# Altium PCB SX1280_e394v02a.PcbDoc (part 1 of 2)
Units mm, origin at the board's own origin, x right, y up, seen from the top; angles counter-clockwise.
Board outline 104.5 x 58 mm, 4 copper layers (Top Layer, MidLayer1, MidLayer2, Bottom Layer), stack 0.995 mm thick; 155 components, 106 nets, 471 pads, 1470 vias.
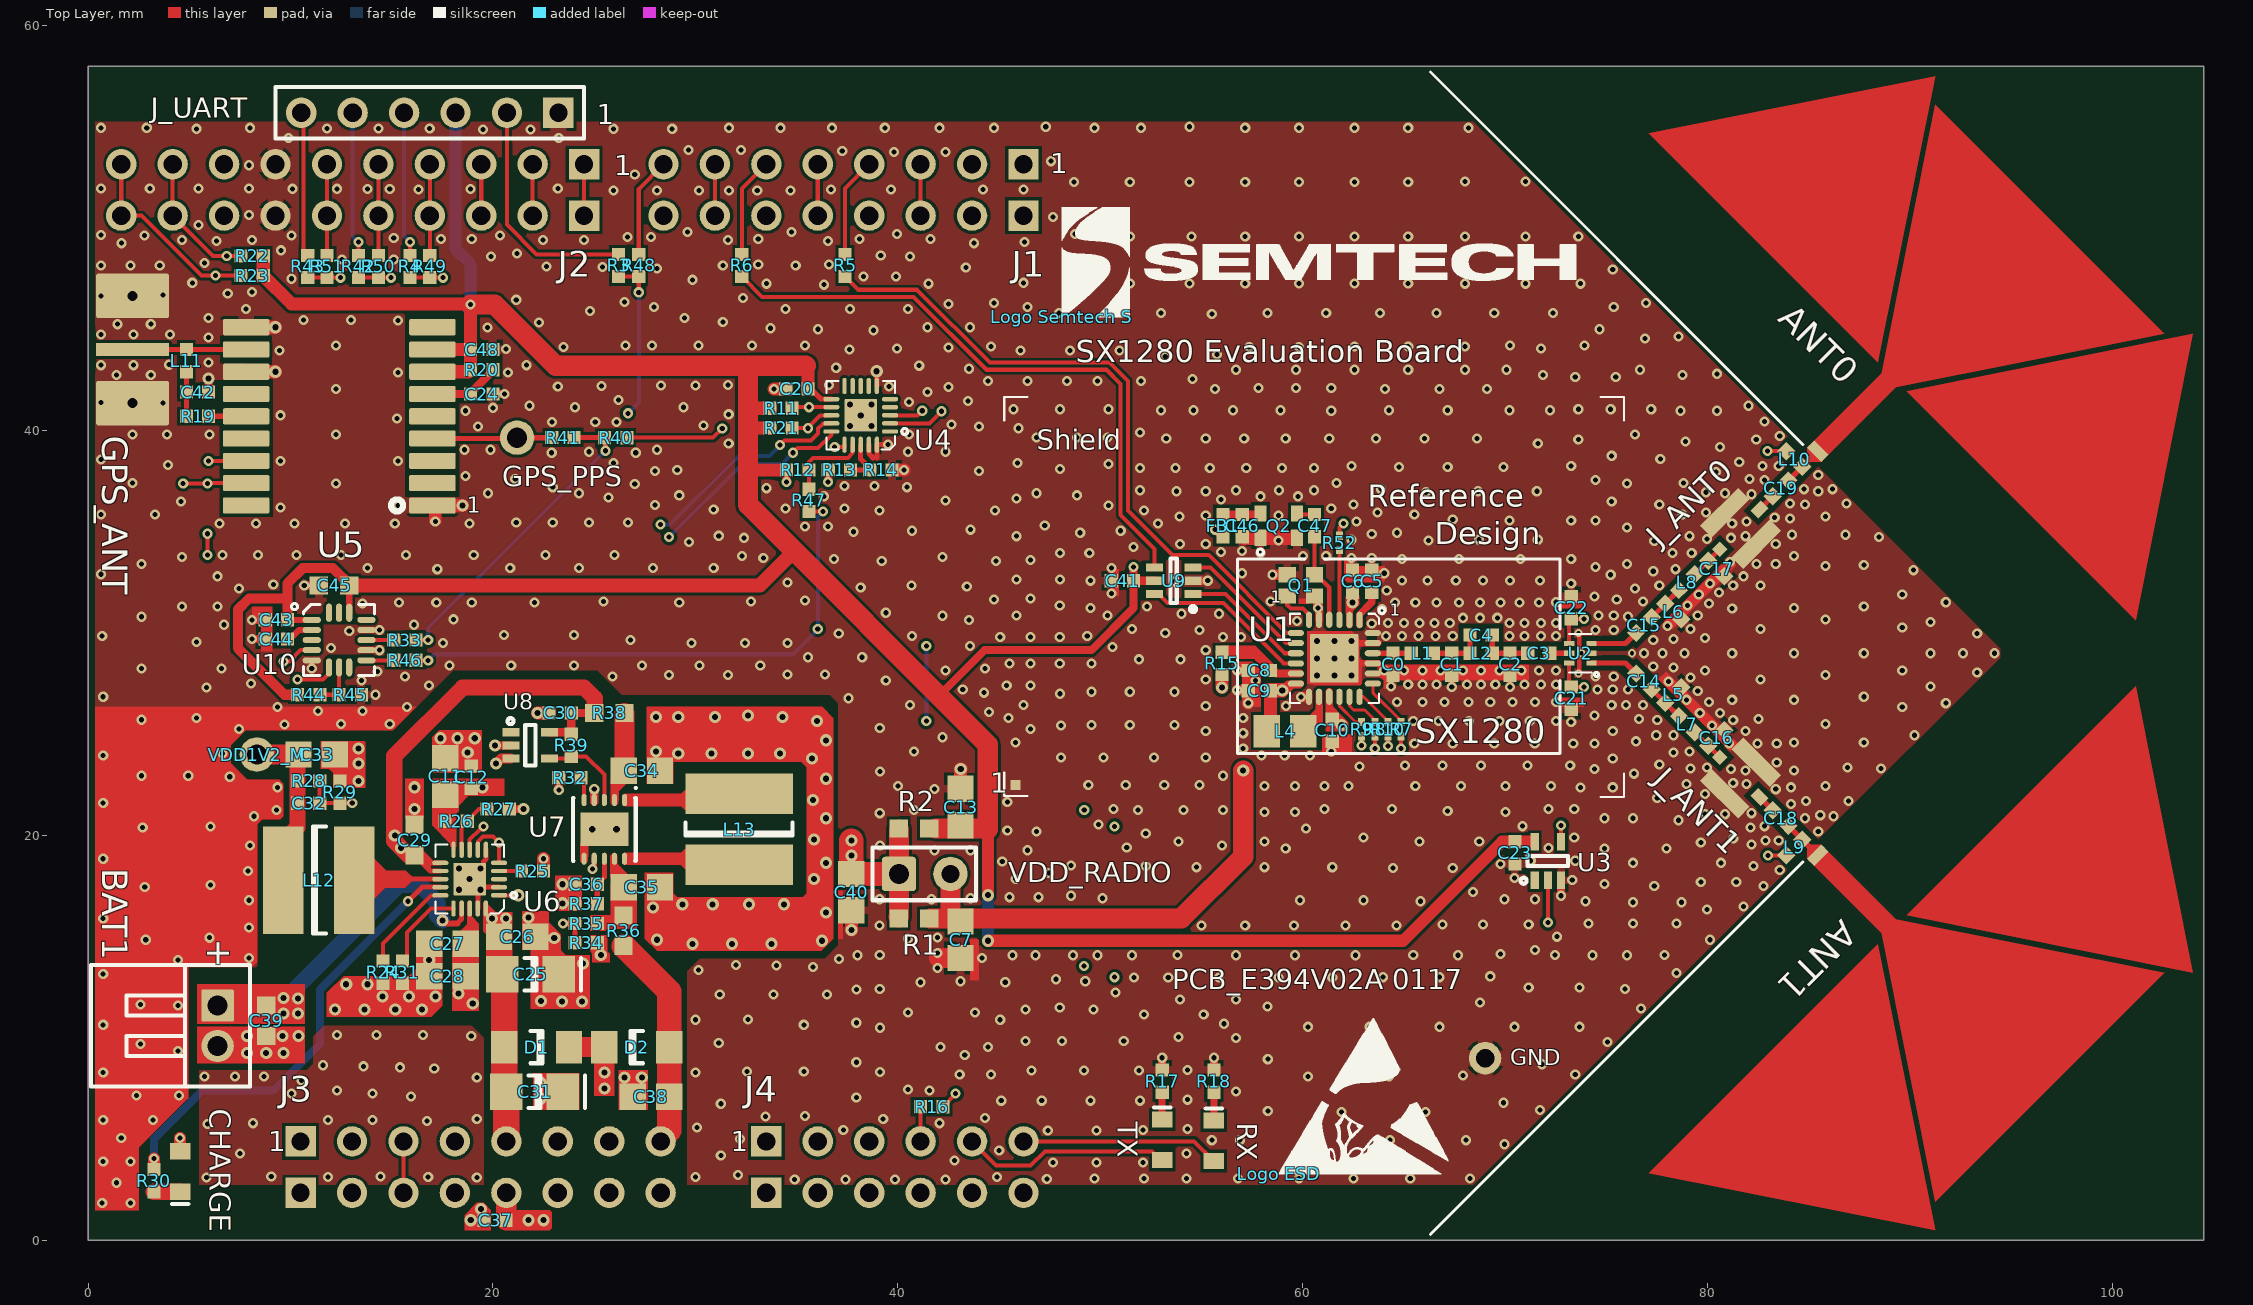
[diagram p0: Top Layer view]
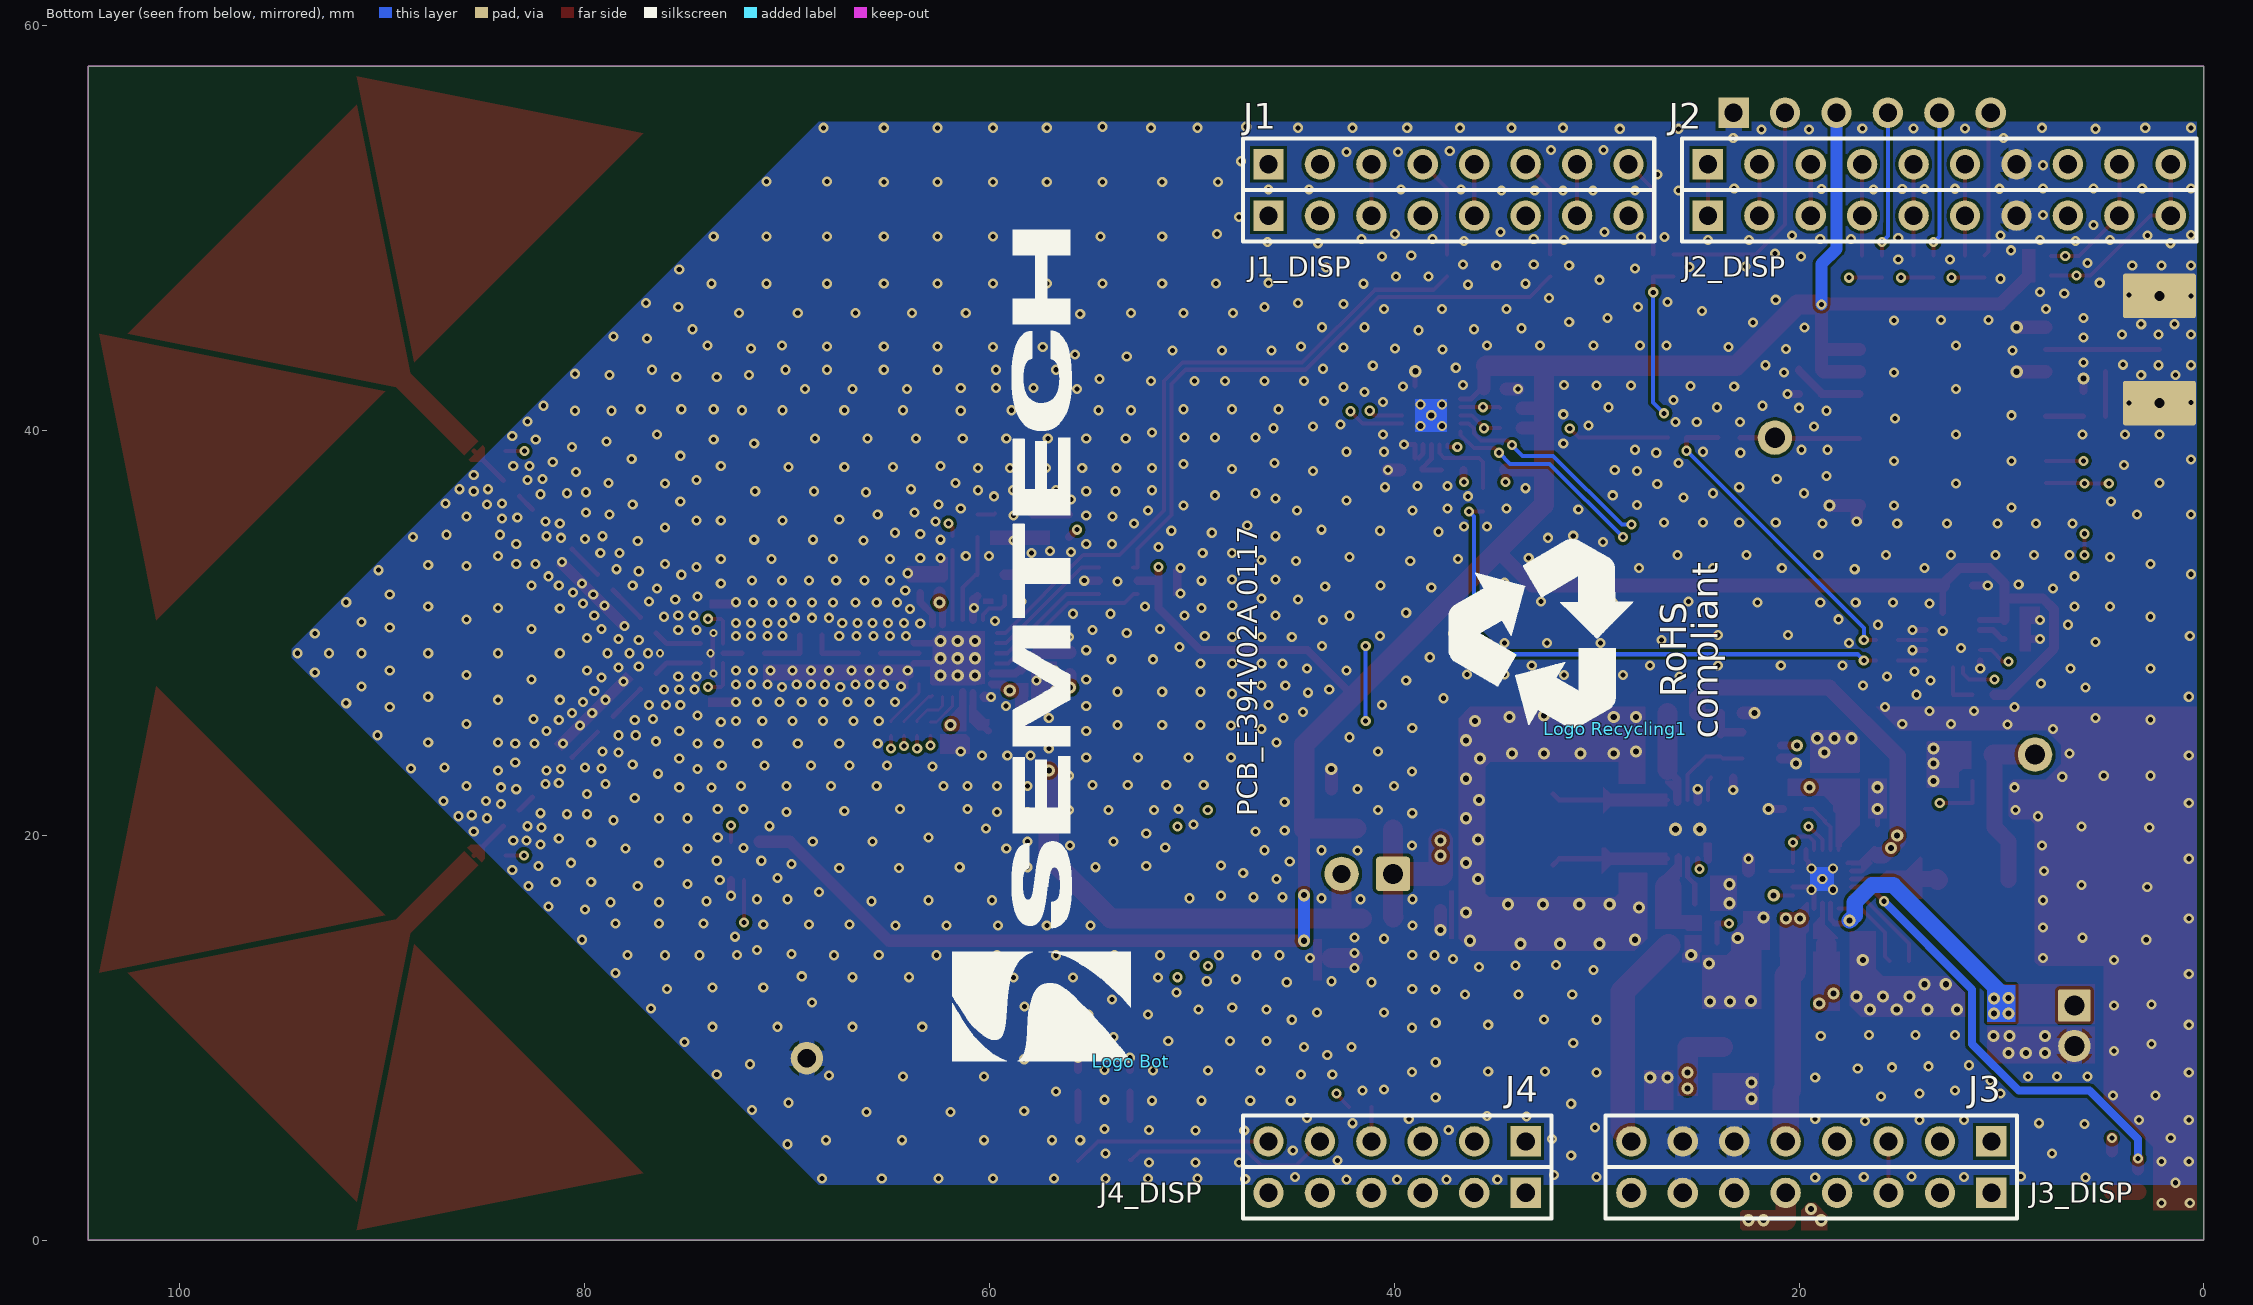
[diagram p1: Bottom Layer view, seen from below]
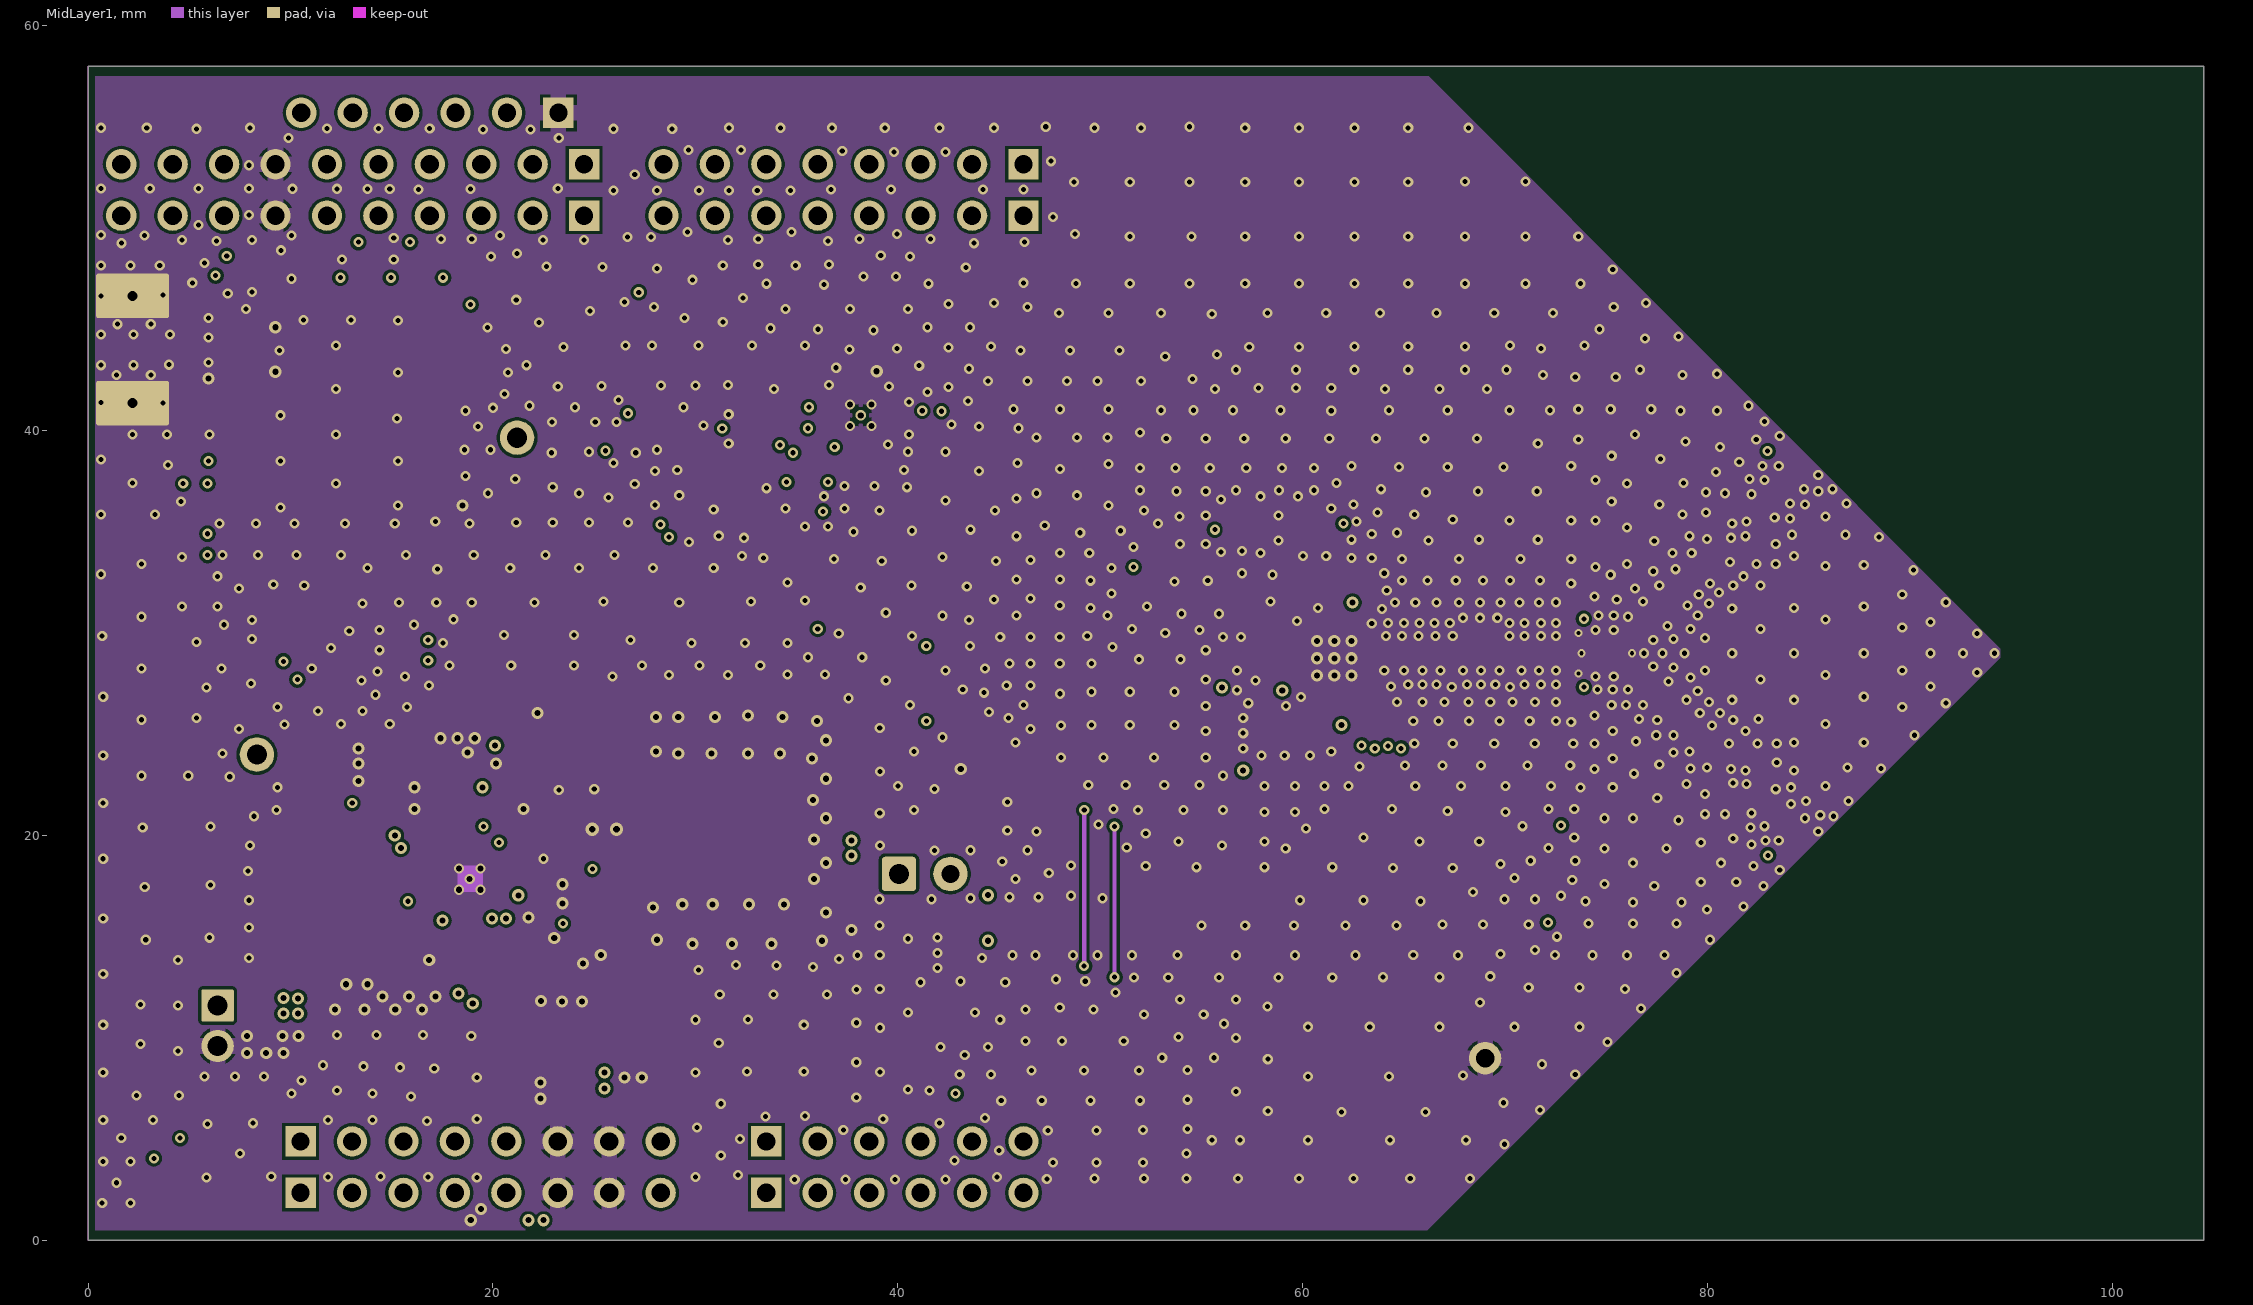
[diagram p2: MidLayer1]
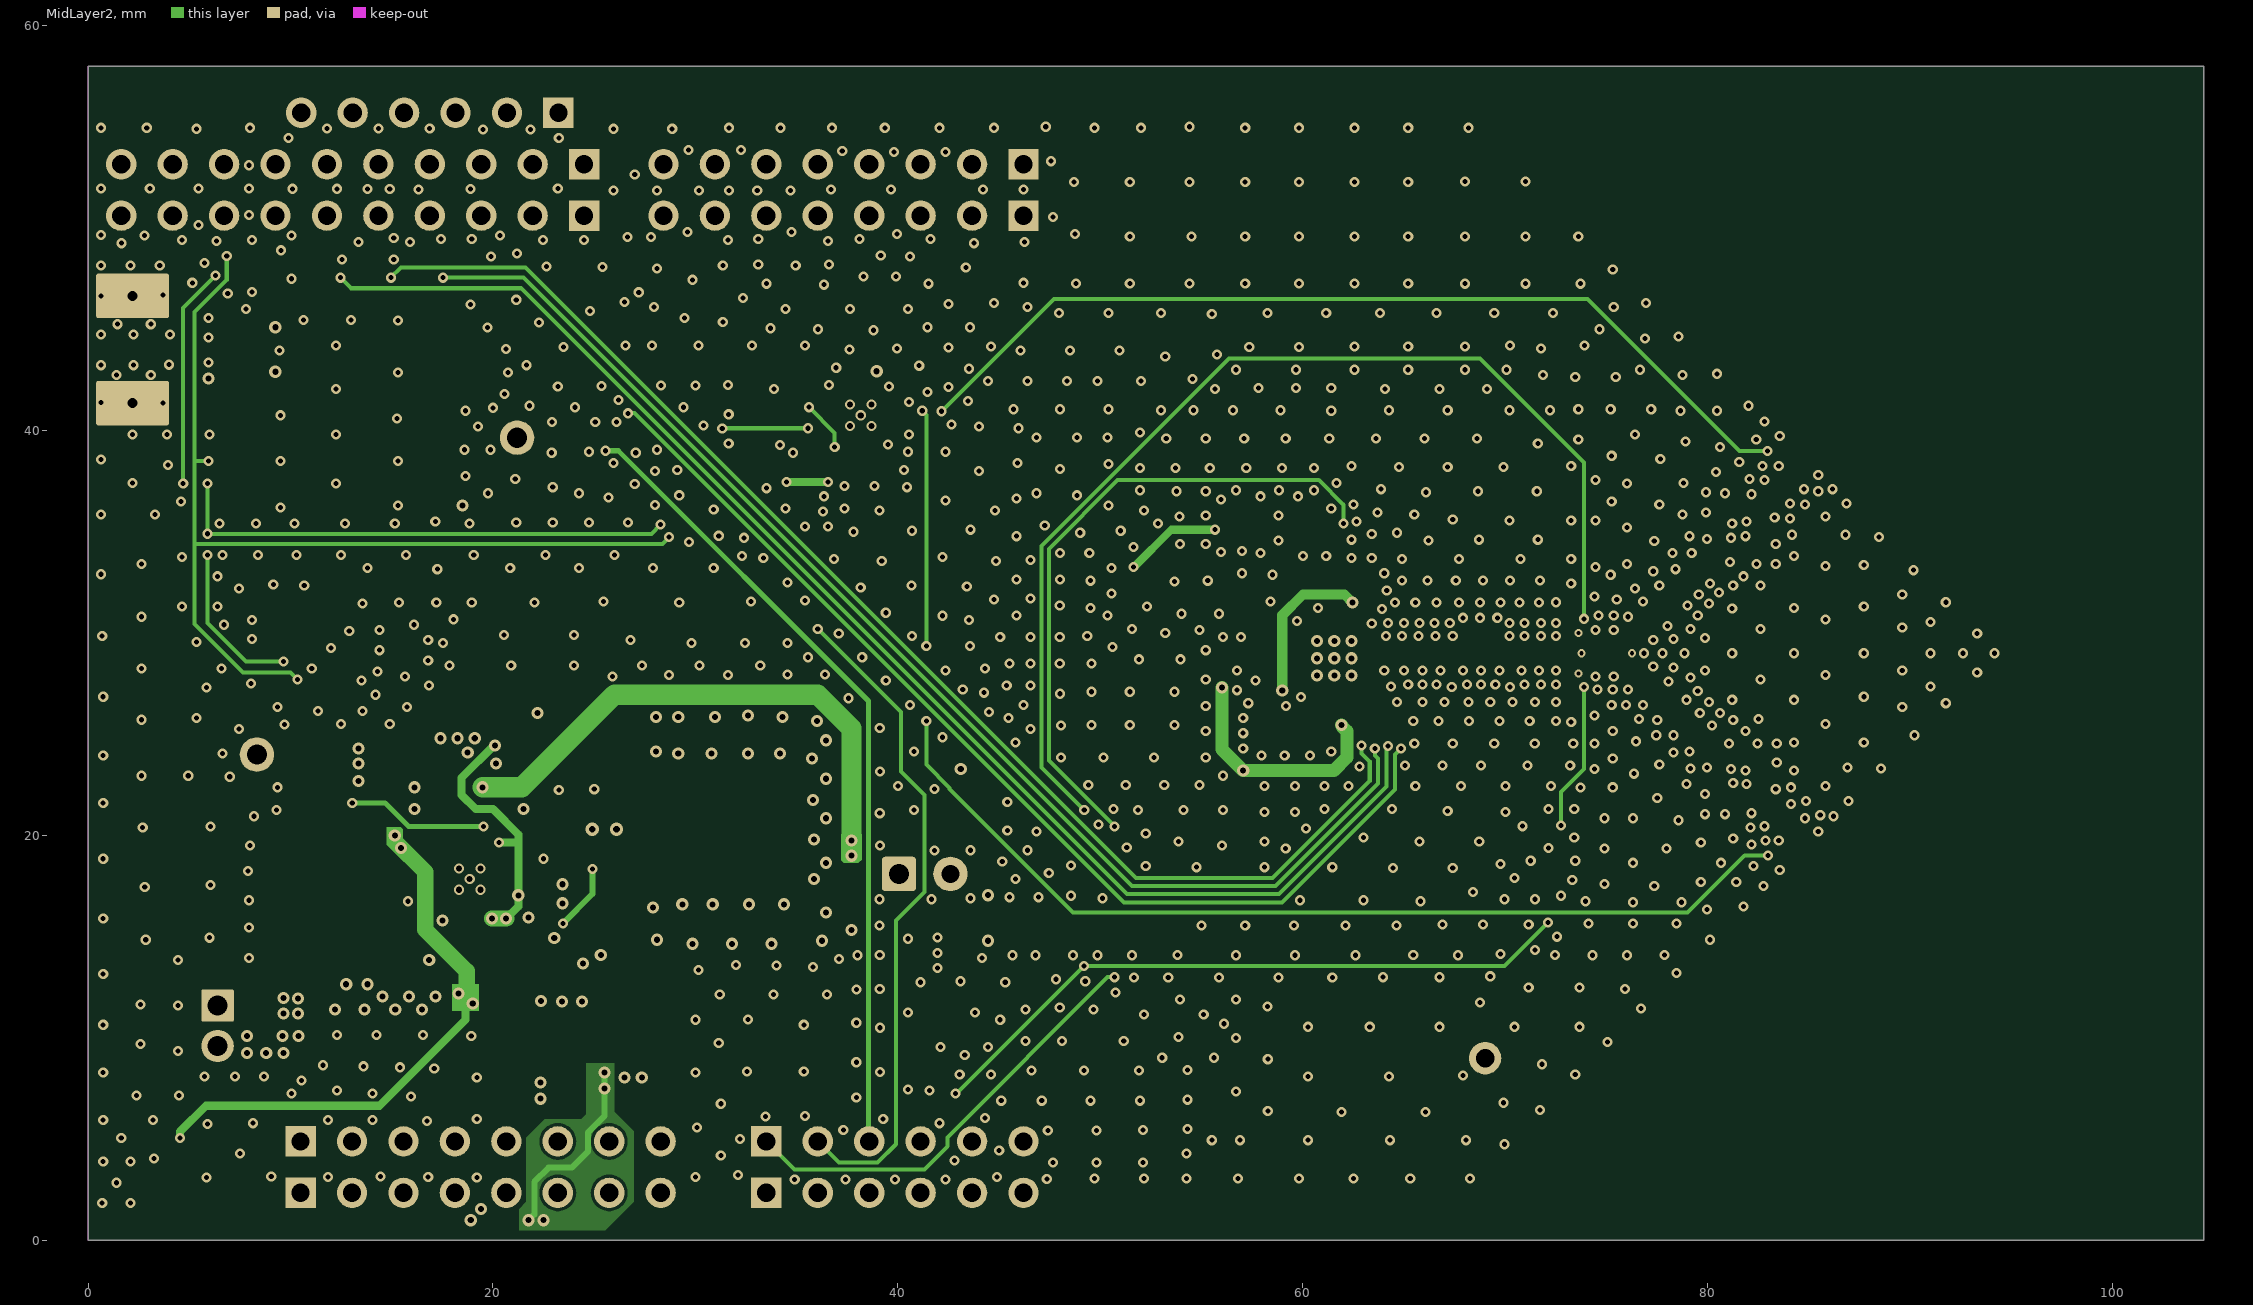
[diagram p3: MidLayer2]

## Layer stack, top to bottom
Top Layer: signal copper 0.035
Dielectric: core 0.127, FR-4, Dk 4.3
MidLayer1: signal copper 0.0356
Dielectric: prepreg 0.6, FR-4, Dk 4.8
MidLayer2: signal copper 0.0356
Dielectric: core 0.127, FR-4, Dk 4.8
Bottom Layer: signal copper 0.035

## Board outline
0,0 0,58 104.5,58 104.5,0

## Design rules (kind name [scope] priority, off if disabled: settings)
Clearance Clearance_RF_GND [InNet('GND') And OnLayer('Top Layer') And (InPolygon) vs InNet('NetC0_1') or InNet('NetC1_2')  or  InNet('NetC2_2') or InNet('NetC3_2')  or  InNet('NetC15_2')  or  InNet('NetC15_1')  or  InNet('NetC17_1') or  InNet('NetC19_2')  or  InNet('NetANT0_1')  or  InNet('NetC14_2')  or  InNet('NetC14_1')  or  InNet('NetC16_1') or  InNet('NetC18_2')  or  InNet('NetANT1_1')] p1: gap=0.25
Clearance Clearance_GND_Keepout [InNet('GND') vs OnLayer('Keep-Out Layer')] p2: gap=0.25
Clearance Clearance_GND [InNet('GND')] p3: gap=0.15
Clearance [All] p4: gap=0.15
ComponentClearance ComponentClearance_SMA_RFIO [InComponent('RFIO')] p1: gap=0 collisioncheckmode=3 verticalgap=0 showdistances=FALSE
ComponentClearance [All] p2: gap=0.2 collisioncheckmode=3 verticalgap=0.3 showdistances=FALSE
HoleSize [All] p1: absolutevalues=TRUE maxlimit=3.6 minlimit=0.2 maxpercent=80.000 minpercent=20.000
HoleToHoleClearance [All] p1: gap=0.2 allowstackedmicrovias=TRUE
MinimumSolderMaskSliver [All] p1: minsoldermaskwidth=0.04
PlaneClearance [All] p1: clearance=0.2
PlaneConnect [All] p1: planeconnectstyle=Direct reliefexpansion=0.508 reliefentries=4 reliefconductorwidth=0.254 reliefairgap=0.254
PolygonConnect "PolygonConnect SMD" [InNet('GND') vs HasFootprint('ND2016DA') or HasFootprint('rlc_603_smd') or HasFootprint('rlc_402_smd') or HasFootprint('rlc_402_smd diode') or hasFootprint('rlc_805_smd')  or hasFootprint('SC70-5')  or hasFootprint('TCXO 2.0x1.6mm')] p1: connectstyle=Relief reliefconductorwidth=0.4 reliefentries=4 polygonreliefangle="90 Angle"
PolygonConnect PolygonConnect_comp_diverse [InNet('GND') or  InNet('VDD') or  InNet('VDD_DISPLAY')  or  InNet('VDD_RADIO') vs HasFootprint('LGM676 LED') or  HasFootprint('BRIDGE_254MM') or  HasFootprint('pin_0.9mm') or HasFootprint('SMA_STRAIGHT')  or  HasFootprint('HDR2X8')   or  HasFootprint('HDR2X6')  or  HasFootprint('HDR1X10') or  HasFootprint('vqfn20_3x3mm') or  HasFootprint('HDR1X9') or  HasFootprint('HDR1X8')  or  HasFootprint('HDR1X6') or  HasFootprint('HDR1X4')   or  HasFootprint('MAX-7') or  HasFootprint('S2B-PH-K-S') or  HasFootprint('DD10_L')] p2: connectstyle=Relief reliefconductorwidth=0.8 reliefentries=4 polygonreliefangle="90 Angle"
PolygonConnect PolygonConnect_all [All] p3: connectstyle=Direct reliefconductorwidth=0.6 reliefentries=4 polygonreliefangle="90 Angle"
RoomDefinition SX1280_Power_Display_e394v02a [InComponentClass('SX1280_Power_Display_e394v02a')] p1: confinementstyle=ConfineOut formatcopy=TRUE lockcomponents=FALSE outline 81.8,81 81.8,123.8 82,124 122,124 122,81
RoomDefinition SX1280_e394v02a [InComponentClass('SX1280_e394v02a')] p2: confinementstyle=ConfineOut formatcopy=TRUE lockcomponents=FALSE outline 13.5,81.35 13.45,81.4 13.45,124.35 67.45,124.35 67.3,124.2 67.3,81.35
RoutingVias [All] p1: holewidth=0.3 width=0.6 viastyle="Through Hole" minholewidth=0.2 minwidth=0.4 maxholewidth=0.4 maxwidth=0.8
SilkToSilkClearance [All] p1: silktosilkclearance=0.05
SilkscreenOverComponentPads [All] p1: minsilkscreentomaskgap=0.05
SolderMaskExpansion [All] p1: expansion=0.05
Width "Width GND" [InNet('GND')] p1: maxlimit=3 minlimit=0.2 preferedwidth=0.4
Width Width_VCC [InNet('VDD') or  InNet('VDD_DISPLAY') or  InNet('VDD_RADIO')] p2: maxlimit=2 minlimit=0.2 preferedwidth=0.8
Width "Width All" [All] p3: maxlimit=2 minlimit=0.15 preferedwidth=0.2
20 further rules are at their usual default settings.

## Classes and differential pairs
component class SX1280_Power_Display_e394v02a: BAT1 C11 C12 C24 C25 C26 C27 C28 C29 C30 C32 C33 C34 C35 C36 C37 C39 C42 C43 C44 C45 C46 C47 C48 CHARGE D1 D2 FB1 GPS_ANT GPS_PPS J1_DISP J2_DISP J3_DISP J4_DISP L11 L12 L13 Q2 R19 R20 R24 R25 R26 R27 R28 R29 R30 R31 R32 R33 R34 R35 R36 R37 R38 R39 R41 R44 R45 R46 U5 U6 U7 U8 U10 VDD1V2_M
component class SX1280_e394v02a: ANT0 ANT1 C0 C1 C2 C3 C4 C5 C6 C7 C8 C9 C10 C13 C14 C15 C16 C17 C18 C19 C20 C21 C22 C23 C31 C38 C40 C41 GND J1 J2 J3 J4 J_ANT0 J_ANT1 J_UART L1 L2 L4 L5 L6 L7 L8 L9 L10 "Logo Bot" "Logo ESD" "Logo Recycling1" "Logo Semtech S" Q1 R1 R2 R3 R4 R5 R6 R7 R8 R9 R10 R11 R12 R13 R14 R15 R16 R17 R18 R21 R22 R23 R40 R42 R43 R47 R48 R49 R50 R51 R52 RFIO RX Shield TX U1 U2 U3 U4 U9 VDD_RADIO

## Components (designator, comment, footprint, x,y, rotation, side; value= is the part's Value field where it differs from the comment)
ANT0 "Antenna" ANT_2.4GHz_microstrip 85.43,38.98 r315 top locked
ANT1 "Antenna" ANT_2.4GHz_microstrip 85.43,19.02 r225 top locked
BAT1 "Battery" S2B-PH-K-S 6.4,11.6 r270 top
C0 "Cap" RLC_402_SMD 64.45,28.45 r270 top
C1 "Cap" RLC_402_SMD 67.35,28.45 r90 top
C2 "Cap" RLC_402_SMD 70.228,28.45 r90 top
C3 "Cap" RLC_402_SMD 71.65,29 r0 top
C4 "Cap" RLC_402_SMD 68.8,29.9 r0 top
C5 "Cap" rlc_402_smd 63.4,32.55 r270 top
C6 "Cap" RLC_402_SMD 62.45,32.55 r270 top
C7 "Cap" rlc_805_smd 43.09,14.85 r90 top
C8 "Cap" RLC_402_SMD 57.85,28.15 r0 top
C9 "Cap" RLC_402_SMD 57.85,27.15 r0 top
C10 "Cap" RLC_402_SMD 61.45,25.2 r90 top
C11 "Cap" rlc_805_smd 17.649,22.917 r270 top
C12 "Cap" RLC_402_SMD 18.925,22.884 r270 top
C13 "Cap" rlc_805_smd 43.09,21.4 r270 top
C14 "Cap" RLC_402_SMD 76.839,27.611 r135 top
C15 "Cap" RLC_402_SMD 76.839,30.389 r225 top
C16 "Cap" RLC_402_SMD 80.41,24.818 r45 top
C17 "Cap" RLC_402_SMD 80.41,33.182 r315 top
C18 "Cap" RLC_402_SMD 83.592,20.858 r135 top
C19 "Cap" RLC_402_SMD 83.592,37.142 r225 top
C20 "Cap" RLC_402_SMD 35.011,42.05 r180 top
C21 "Cap" RLC_402_SMD 73.25,26.775 r90 top
C22 "Cap" RLC_402_SMD 73.25,31.25 r270 top
C23 "Cap" RLC_402_SMD 70.47,19.139 r90 top
C24 "Cap" RLC_402_SMD 19.445,41.8 r0 top
C25 "Cap Pol" CD3216-1206 21.85,13.144 r0 top
C26 "Cap" rlc_805_smd 21.2,14.994 r180 top
C27 "Cap" rlc_805_smd 17.75,14.644 r0 top
C28 "Cap" rlc_805_smd 17.75,13.044 r0 top
C29 "Cap" rlc_603_smd 16.125,19.775 r270 top
C30 "Cap" RLC_402_SMD 23.317,26.05 r0 top
C31 "Cap Pol" CD3216-1206 22.05,7.35 r0 top
C32 "Cap" RLC_402_SMD 10.892,21.594 r180 top
C33 "Cap" rlc_805_smd 11.292,23.994 r180 top
C34 "Cap" rlc_805_smd 27.35,23.2 r180 top
C35 "Cap" rlc_805_smd 27.35,17.45 r180 top
C36 "Cap" RLC_402_SMD 24.6,17.589 r0 top
C37 "Cap" RLC_402_SMD 20.1,1 r0 top
C38 "Cap" rlc_805_smd 27.8,7.1 r0 top
C39 "Cap" rlc_603_smd 8.8,10.85 r90 top
C40 "Cap" rlc_805_smd 37.7,17.2 r90 top
C41 "Cap" RLC_402_SMD 51.084,32.58 r0 top
C42 "Cap" RLC_402_SMD 5.407,41.9 r0 top
C43 "Cap" RLC_402_SMD 9.3,30.65 r0 top
C44 "Cap" RLC_402_SMD 9.3,29.7 r0 top
C45 "Cap" rlc_603_smd 12.15,32.35 r0 top
C46 "Cap" RLC_402_SMD 57,35.3 r90 top
C47 "Cap" RLC_402_SMD 60.575,35.3 r270 top
C48 "Cap" RLC_402_SMD 19.445,44 r0 top
CHARGE "LED" "LGM676 LED" 4.55,3.4 r270 top
D1 "D Schottky single" SOD123 22.15,9.55 r0 top
D2 "D Schottky single" SOD123 27.1,9.55 r180 top
FB1 "Ferrite beads" RLC_402_SMD 56.05,35.3 r90 top
GND "Test Pin" pin_0.9mm 69,9 r90 top
GPS_ANT "SMA End Launch" "SMA END LAUNCH JACK RECEPTACLE SHORT" 1.8,44 r270 top
GPS_PPS "Test Pin" pin_1mm 21.19,39.645 r90 top
J1 "Header 8" HDR1X8 46.2,53.15 r180 bottom locked
J1_DISP "Header 8" HDR1X8 46.2,50.61 r180 bottom locked
J2 "Header 10" HDR1X10 24.5,53.15 r180 bottom locked
J2_DISP "Header 10" HDR1X10 24.5,50.61 r180 bottom locked
J3 "Header 8" HDR1X8 10.5,4.89 r0 bottom locked
J3_DISP "Header 8" HDR1X8 10.5,2.35 r0 bottom locked
J4 "Header 6" HDR1X6 33.5,4.89 r0 bottom locked
J4_DISP "Header 6" HDR1X6 33.5,2.35 r0 bottom locked
J_ANT0 "MS-156HF" "MS-156HF Hirose" 81.665,35.215 r225 top
J_ANT1 "MS-156HF" "MS-156HF Hirose" 81.665,22.785 r135 top
J_UART "Header 6" HDR1X6 23.23,55.69 r180 top locked
L1 "Inductor" RLC_402_SMD 65.9,29 r0 top
L2 "Inductor" RLC_402_SMD 68.8,29 r0 top
L4 "Inductor" "rlc_805_smd enlarged" 59.12,25.15 r0 top
L5 "Inductor" RLC_402_SMD 78.288,26.939 r225 top
L6 "Inductor" RLC_402_SMD 78.288,31.061 r135 top
L7 "Inductor" RLC_402_SMD 78.96,25.49 r315 top
L8 "Inductor" RLC_402_SMD 78.96,32.51 r45 top
L9 "Inductor" RLC_402_SMD 84.263,19.408 r45 top
L10 "Inductor" RLC_402_SMD 84.263,38.59 r315 top
L11 "Inductor" RLC_402_SMD 4.857,43.45 r270 top
L12 "Inductor" L4818 11.4,17.8 r270 top
L13 "Inductor" L4818 32.15,20.3 r0 top
"Logo Bot" "Logo symbol" logo_semtech_horiz_size4 53,8.85 r90 bottom
"Logo ESD" "Logo symbol" "Logo ESD" 58.8,3.3 r0 top
"Logo Recycling1" "Logo symbol" "Logo Recycling1" 29.077,25.27 r90 bottom
"Logo Semtech S" "Logo symbol" logo_semtech_horiz_size3 48.1,45.61 r0 top
Q1 "Xtal" ND2016DA 59.9,32.35 r0 top
Q2 "TCXO" "TCXO 2.0x1.6mm" 58.8,35.3 r0 top
R1 "Resistor" rlc_603_smd 40.79,15.9 r180 top
R2 "Resistor" rlc_603_smd 40.79,20.35 r180 top
R3 "Resistor" RLC_402_SMD 26.2,48.15 r270 top
R4 "Resistor" RLC_402_SMD 15.9,48.1 r270 top
R5 "Resistor" RLC_402_SMD 37.39,48.15 r270 top
R6 "Resistor" RLC_402_SMD 32.286,48.15 r270 top
R7 "Resistor" rlc_201_smd 64.85,25.25 r90 top
R8 "Resistor" rlc_201_smd 63.55,25.25 r90 top
R9 "Resistor" rlc_201_smd 62.9,25.25 r90 top
R10 "Resistor" rlc_201_smd 64.2,25.25 r90 top
R11 "Resistor" RLC_402_SMD 34.225,41.1 r0 top
R12 "Resistor" RLC_402_SMD 35.05,38.05 r180 top
R13 "Resistor" RLC_402_SMD 37.111,38.05 r180 top
R14 "Resistor" RLC_402_SMD 39.161,38.05 r180 top
R15 "Resistor" RLC_402_SMD 56,28.5 r270 top
R16 "Resistor" RLC_402_SMD 41.667,6.6 r180 top
R17 "Resistor" RLC_402_SMD 53.05,7.871 r270 top
R18 "Resistor" RLC_402_SMD 55.6,7.871 r270 top
R19 "Resistor" RLC_402_SMD 5.407,40.7 r180 top
R20 "Resistor" RLC_402_SMD 19.445,43 r0 top
R21 "Resistor" RLC_402_SMD 34.225,40.125 r180 top
R22 "Resistor" RLC_402_SMD 8.1,48.625 r0 top
R23 "Resistor" RLC_402_SMD 8.1,47.65 r0 top
R24 "Resistor" RLC_402_SMD 14.575,13.25 r270 top
R25 "Resistor" RLC_402_SMD 21.95,18.244 r0 top
R26 "Resistor" RLC_402_SMD 18.18,20.7 r0 top
R27 "Resistor" RLC_402_SMD 20.25,21.3 r0 top
R28 "Resistor" RLC_402_SMD 10.892,22.694 r0 top
R29 "Resistor" RLC_402_SMD 12.442,22.144 r90 top
R30 "Resistor" RLC_402_SMD 3.25,2.95 r270 top
R31 "Resistor" RLC_402_SMD 15.531,13.25 r270 top
R32 "Resistor" RLC_402_SMD 23.8,22.85 r180 top
R33 "Resistor" RLC_402_SMD 15.65,29.65 r0 top
R34 "Resistor" RLC_402_SMD 24.6,14.7 r180 top
R35 "Resistor" RLC_402_SMD 24.6,15.65 r0 top
R36 "Resistor" rlc_603_smd 26.45,15.294 r270 top
R37 "Resistor" RLC_402_SMD 24.6,16.625 r0 top
R38 "Resistor" rlc_603_smd 25.75,26.05 r0 top
R39 "Resistor" RLC_402_SMD 23.867,24.45 r270 top
R40 "Resistor" RLC_402_SMD 26.062,39.645 r0 top
R41 "Resistor" RLC_402_SMD 23.45,39.65 r0 top
R42 "Resistor" RLC_402_SMD 13.35,48.1 r270 top
R43 "Resistor" RLC_402_SMD 10.85,48.1 r270 top
R44 "Resistor" RLC_402_SMD 10.9,26.95 r0 top
R45 "Resistor" RLC_402_SMD 12.95,26.95 r0 top
R46 "Resistor" RLC_402_SMD 15.65,28.65 r0 top
R47 "Resistor" RLC_402_SMD 35.6,36.55 r90 top
R48 "Resistor" RLC_402_SMD 27.2,48.15 r270 top
R49 "Resistor" RLC_402_SMD 16.88,48.1 r270 top
R50 "Resistor" RLC_402_SMD 14.34,48.1 r270 top
R51 "Resistor" RLC_402_SMD 11.8,48.1 r270 top
R52 "Resistor" rlc_201_smd 61.8,34.45 r90 top
RX "LED" "LGM676 LED" 55.6,4.921 r90 top
Shield "Logo symbol" "BMIS-209-F - SHIELD" 45.8,22.5 r0 top locked
TX "LED" "LGM676 LED" 53.05,4.971 r90 top
U1 "SX1280" VQFN24_4X4MM 61.55,28.75 r270 top locked
U2 "RF Switch" MiniMold-6 73.7,29 r90 top
U3 "NC7SZ04" SC70-5 72.1,18.739 r90 top
U4 "SX9306" vqfn20_3x3mm 38.161,40.75 r180 top
U5 "MAX-7Q GPS" MAX-7 12.41,40.7 r0 top
U6 "LTC3553" vqfn20_3x3mm 18.85,17.844 r180 top
U7 "LTC3127" DD10_L 25.5,20.3 r270 top
U8 "NC7SZ04" SC70-5 21.842,24.446 r0 top
U9 "74LVC1G332GW" SOT363-6 53.619,32.58 r180 top
U10 "MMA8451Q" VQFN16_3X3MM 12.4,29.65 r0 top
VDD1V2_M "Test Pin" pin_1mm 8.342,23.994 r270 top
VDD_RADIO "Jumper" BRIDGE_254MM 40.05,18.1 r0 top

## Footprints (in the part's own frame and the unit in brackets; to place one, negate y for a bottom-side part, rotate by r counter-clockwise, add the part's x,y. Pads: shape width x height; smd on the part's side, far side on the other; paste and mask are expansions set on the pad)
ANT_2.4GHz_microstrip [mm] "Antenna 2.4 GHz ISM band - Microstrip"
  rect 1x0.5 smd paste-1 mask-1: 1(0,0)
  Top Layer region: 8,16.2 -8,16.2 -0.5,4.95 -0.5,0.2 0.5,0.2 0.5,4.95
  Top Layer region: 1,5.2 17,5.2 9,17.2
  Top Layer region: -17,5.2 -1,5.2 -9,17.2
  body extent -0.5,-0.25 0.5,0.2, height 2.95
"BMIS-209-F - SHIELD" [mm] "BMIS-209-F EMI Gasket - modif SolderMask - Standard Surface Mount Shields -  Laird Technologies"
  rect 0.5x0.5 smd paste-1 mask+0.05: 1(0,0)
  Mechanical 15 keep-out lines w1: 0,0 29.5,0 29.5,18.6 0,18.6 0,0
  silkscreen extent -0.55,-0.6 30.05,19.15, body extent -0.3,-0.3 0.3,0.3, height 0.8
BRIDGE_254MM [mm] "Generic Bridge 2.54mm, 2 Leads 0.9mm;"
  rrect20% 1.7x1.7 hole 1 paste+0 mask+0.05: 1(0,0)
  round 1.7 hole 0.9 paste+0 mask+0.05: 2(2.54,0)
  silkscreen extent -1.3,-1.3 3.8,1.3, body extent -1.4,-1.4 3.9,1.4, height 1
CD3216-1206 [mm] "Chip Diode; Body 3.2 x 1.6 mm (LxW typ)"
  rect 1.6x1.8 smd mask+0.05: 1(-1.4,0) 2(1.4,0)
  silkscreen extent -0.3,-0.8 2.5,0.8
DD10_L [mm] "SON, 10-Leads, Body 3x3 mm, Pitch 0.5mm, IPC High Density"
  oval 0.6x0.25 smd: 1(-1.45,1) 2(-1.45,0.5) 3(-1.45,0) 4(-1.45,-0.5) 5(-1.45,-1) 6(1.45,-1) 7(1.45,-0.5) 8(1.45,0) 9(1.45,0.5) 10(1.45,1)
  rect 1.65x2.38 smd: 11(0,0)
  silkscreen extent -2.1,-1.55 1.55,1.6, body extent -1.55,-1.55 1.55,1.55, height 0.8
HDR1X6 [mm] "Connector; Header; 6 Position"
  rect 1.5x1.5 hole 0.9: 1(0,0)
  round 1.5 hole 0.9: 2(2.54,0) 3(5.08,0) 4(7.62,0) 5(10.16,0) 6(12.7,0)
  silkscreen extent -1.27,-1.27 13.97,1.27, body extent -0.8,-0.8 13.5,0.8
HDR1X8 [mm] "Connector; Header; 8 Position"
  rect 1.5x1.5 hole 0.9: 1(0,0)
  round 1.5 hole 0.9: 2(2.54,0) 3(5.08,0) 4(7.62,0) 5(10.16,0) 6(12.7,0) 7(15.24,0) 8(17.78,0)
  silkscreen extent -1.27,-1.27 19.05,1.27, body extent -0.8,-0.8 18.58,0.8
HDR1X10 [mm] "Connector; Header; 10 Position"
  rect 1.5x1.5 hole 0.9: 1(0,0)
  round 1.5 hole 0.9: 2(2.54,0) 3(5.08,0) 4(7.62,0) 5(10.16,0) 6(12.7,0) 7(15.24,0) 8(17.78,0) 9(20.32,0) 10(22.86,0)
  silkscreen extent -1.27,-1.27 24.13,1.27, body extent -0.8,-0.8 23.66,0.8
L4818 [mil] "L4818"
  rect 209x79 smd mask+1.97: 1(0,69.03) 2(0,-69.03)
  silkscreen extent -104,-12 104,14, body extent -106,-110 106,110, height 197
"LGM676 LED" [mm] "Chip Diode; Body 2.1 x 1.4 mm (LxW typ)"
  rect 0.8x1 smd mask+0.05: 1(-1,0) 2(1,0)
  silkscreen extent 1.6,-0.4 1.6,0.4, body extent -1.2,-0.7 1.2,0.7, height 12
"Logo ESD" [mm] "Logo ESD"
  silkscreen extent 0,0 8.38,7.67
"Logo Recycling1" [mm] "Logo Recycling1"
  silkscreen extent 0.05,-0.88 9.36,8.2
logo_semtech_horiz_size3 [mm] "Logo semtech horizontal - size3 - L"
  silkscreen extent 0,0 25.4,5.41
logo_semtech_horiz_size4 [mm] "Logo semtech horizontal - size4 - XL"
  silkscreen extent 0,0 41.07,8.79
MAX-7 [mm] "MAX-7; GPS U-Blox footprint"
  rrect20% 2.3x0.8 smd mask+0.05: 1(4.6,-4.4) 2(4.6,-3.3) 3(4.6,-2.2) 4(4.6,-1.1) 5(4.6,0) 6(4.6,1.1) 7(4.6,2.2) 8(4.6,3.3) 9(4.6,4.4) 10(-4.6,4.4) 11(-4.6,3.3) 12(-4.6,2.2) 13(-4.6,1.1) 14(-4.6,0) 15(-4.6,-1.1) 16(-4.6,-2.2) 17(-4.6,-3.3) 18(-4.6,-4.4)
  silkscreen extent 2.55,-4.7 3.15,-4.1, body extent -4.9,-5.2 4.9,5.2, height 2.95
MiniMold-6 [mm] "MiniMold-6 Package 1.5x1.1mm"
  rect 0.26x0.5 smd mask+0.05: 1(-0.48,-0.55) 2(0,-0.55) 3(0.48,-0.55) 4(0.48,0.55) 5(0,0.55) 6(-0.48,0.55)
  silkscreen extent -1.15,-0.9 0.95,0.55, body extent -0.75,-0.55 0.75,0.55, height 1
"MS-156HF Hirose" [mm] "Hirose MS-156HF receptacle - MS-156HF"
  rect 0.7x0.55 smd mask+0.05: 1(-1.25,0)
  rect 0.55x0.55 smd mask+0.05: 2(1.525,0)
  rect 2.65x0.8 smd mask+0.05: 3(0.075,-1.1) 4(0.075,1.1)
  body extent -1.35,-1.35 1.35,1.35, height 16
ND2016DA [mm] "Crystal SMD 2.0x1.6mm"
  rect 0.85x0.75 smd mask+0.05: 1(-0.675,-0.525) 2(0.675,-0.525) 3(0.675,0.525) 4(-0.675,0.525)
  body extent -1,-0.8 1,0.8, height 1
pin_0.9mm [mm] "Generic Pin 0.9mm; 1 Lead"
  round 1.6 hole 0.9 mask+0.05: 1(0,0)
pin_1mm [mm] "Generic Pin 1.1mm; 1 Lead"
  round 1.7 hole 1 paste+0 mask+0.05: 1(0,0)
rlc_201_smd [mm] "Chip SMD component 201; Body 0.6 x 0.3 mm (LxW typ)"
  rect 0.4x0.35 smd mask+0.05: 1(-0.35,0) 2(0.35,0)
RLC_402_SMD [mm] "Chip SMD component 402; Body 1.0 x 0.5 mm (LxW typ)"
  rect 0.65x0.65 smd mask+0.05: 1(-0.55,0) 2(0.55,0)
  body extent -0.87,-0.33 0.87,0.33, height 0.8
rlc_402_smd [mm] "Chip SMD component 402; Body 1.0 x 0.5 mm (LxW typ)"
  rect 0.65x0.65 smd mask+0.05: 1(-0.55,0) 2(0.55,0)
  body extent -0.87,-0.33 0.87,0.33, height 0.8
rlc_603_smd [mm] "Chip SMD component 603; Body 1.6 x 0.8mm (LxW typ)"
  rect 0.9x0.9 smd paste+0 mask+0.05: 1(-0.75,0) 2(0.75,0)
rlc_805_smd [mm] "Chip SMD component 805; Body 2.0 x 1.25 mm (LxW typ)"
  rect 1.3x1.3 smd mask+0.05: 1(-0.9,0) 2(0.9,0)
"rlc_805_smd enlarged" [mm] "Chip SMD component 805; Body 2.0 x 1.25 mm (LxW typ)"
  rect 1.3x1.6 smd mask+0.05: 1(-0.9,0) 2(0.9,0)
S2B-PH-K-S [mm] "S2B-PH-K-S; JST; Battery Connector side entry; Header; 2 Position"
  rrect10% 1.6x1.6 hole 1: 1(0,0)
  round 1.6 hole 1: 2(2,0)
  silkscreen extent -2,-6.25 4,1.6, body extent -2,-6.25 4,1.6, height 2.95
SC70-5 [mm] "SC70 5-Leads, Body 2.0x1.25mm, Pitch 0.65mm"
  rect 0.85x0.4 smd mask+0.05: 1(-0.95,0.65) 2(-0.95,0) 3(-0.95,-0.65) 4(0.95,-0.65) 5(0.95,0.65)
  silkscreen extent -1.12,-1 0.25,1.35, body extent -0.63,-1 0.63,1, height 1.45
"SMA END LAUNCH JACK RECEPTACLE SHORT" [mm] "SMA Connector - End Launch Jack Receptacle - Short"
  rrect10% 0.65x3.6 smd paste+0 mask+0.05: 1(0,0.4)
  rrect10% 2.2x3.6 hole 0.5 mask+0.1: 2(-2.65,0.4) 2(2.65,0.4)
  body extent -0.33,-0.4 0.33,0.4, height 2.95
SOD123 [mm] "SOD123; Chip Diode; Body  2.7 x 1.6 mm (LxW typ)"
  rect 1.3x1.6 smd mask+0.05: 1(-1.6,0) 2(1.6,0)
  silkscreen extent -0.3,-0.8 0.3,0.8
SOT363-6 [mm] "SOT363, 6-Leads, Body 2x1.3mm, Pitch 0.65mm, Lead Span 2.1mm, IPC Medium Density"
  rect 0.85x0.4 smd mask+0.05: 1(-0.95,0.65) 2(-0.95,0) 3(-0.95,-0.65) 4(0.95,-0.65) 5(0.95,0) 6(0.95,0.65)
  silkscreen extent -1.07,-1.1 0.15,1.52, body extent -0.7,-1.1 0.7,1.1, height 1
"TCXO 2.0x1.6mm" [mm] "SMD 2.0x1.6mm for TCXO or VCTCXO"
  rect 0.6x0.8 smd mask+0.05: 1(-0.9,-0.6) 2(0.9,-0.6) 3(0.9,0.6) 4(-0.9,0.6)
  silkscreen extent -1.05,-1.45 -0.75,-1.15, body extent -1,-0.8 1,0.8, height 1
VQFN16_3X3MM [mm] "16 Leads, Body 3.0x3.0mm, Pitch 0.50mm, VQFN16"
  oval 0.9x0.3 smd mask+0.05: 1(-1.35,1) 2(-1.35,0.5) 3(-1.35,0) 4(-1.35,-0.5) 5(-1.35,-1) 9(1.35,-1) 10(1.35,-0.5) 11(1.35,0) 12(1.35,0.5) 13(1.35,1)
  oval 0.3x0.9 smd mask+0.05: 6(-0.5,-1.35) 7(0,-1.35) 8(0.5,-1.35) 14(0.5,1.35) 15(0,1.35) 16(-0.5,1.35)
  Mechanical 15 keep-out lines w0.1: -1.95,-1.95 1.95,-1.95 1.95,1.95 -1.95,1.95 -1.95,-1.95
  silkscreen extent -2.35,-1.75 1.75,1.8, body extent -1.5,-1.5 1.5,1.5, height 1
vqfn20_3x3mm [mm] "20 Leads, Body 3.0x3.0mm, Pitch 0.40mm, VQFN20"
  oval 0.8x0.22 smd mask+0.05: 1(-1.45,0.8) 2(-1.45,0.4) 3(-1.45,0) 4(-1.45,-0.4) 5(-1.45,-0.8) 11(1.45,-0.8) 12(1.45,-0.4) 13(1.45,0) 14(1.45,0.4) 15(1.45,0.8)
  oval 0.22x0.8 smd mask+0.05: 6(-0.8,-1.45) 7(-0.4,-1.45) 8(0,-1.45) 9(0.4,-1.45) 10(0.8,-1.45) 16(0.8,1.45) 17(0.4,1.45) 18(0,1.45) 19(-0.4,1.45) 20(-0.8,1.45)
  rrect5% 1.6x1.6 smd paste-2.2 mask+0.05: 21(0,0)
  Mechanical 15 keep-out lines w0.1: 2,2 -2,2 -2,-2 2,-2 2,2
  silkscreen extent -2.32,-1.7 1.7,1.7, body extent -1.5,-1.5 1.5,1.5, height 1
VQFN24_4X4MM [mm] "24 Leads, Body 4.0x4.0mm, Pitch 0.50mm, VQFN24"
  oval 0.8x0.3 smd mask+0.05: 1(-1.9,1.25) 2(-1.9,0.75) 3(-1.9,0.25) 4(-1.9,-0.25) 5(-1.9,-0.75) 6(-1.9,-1.25) 13(1.9,-1.25) 14(1.9,-0.75) 15(1.9,-0.25) 16(1.9,0.25) 17(1.9,0.75) 18(1.9,1.25)
  oval 0.3x0.8 smd mask+0.05: 7(-1.25,-1.9) 8(-0.75,-1.9) 9(-0.25,-1.9) 10(0.25,-1.9) 11(0.75,-1.9) 12(1.25,-1.9) 19(1.25,1.9) 20(0.75,1.9) 21(0.25,1.9) 22(-0.25,1.9) 23(-0.75,1.9) 24(-1.25,1.9)
  rrect5% 2.4x2.4 smd paste-2.5 mask+0.05: 25(0,0)
  Mechanical 15 keep-out lines w0.1: 2.5,-2.5 -2.5,-2.5 -2.5,2.5 2.5,2.5 2.5,-2.5
  silkscreen extent -2.5,-2.2 2.2,2.5, body extent -2,-2 2,2, height 1

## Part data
ANT0 ANT1: "Generic Antenna"
BAT1: "Baterry standard modif"
C0 C1 C2 C3 C4 C5 C6 C7 C8 C9 C10 C11 C12 C13 C14 C15 C16 C17 C18 C19 C20 C21 C22 C23 C24 C26 C27 C28 C29 C30 C32 C33 C34 C35 C36 C37 C38 C39 C40 C41 C42 C43 C44 C45 C46 C47 C48: "Capacitor SMD"
C25 C31: "Polarized Capacitor (Surface Mount)"
D1 D2: "Schottky Diode"
GND GPS_PPS VDD1V2_M: library part test_pin
GPS_ANT: library part SMA, "SMA Straight Connector"
J1 J1_DISP J3 J3_DISP: "Header, 8-Pin"
J2 J2_DISP: "Header, 10-Pin"
J4 J4_DISP J_UART: "Header, 6-Pin"
J_ANT0 J_ANT1: "MS-156HF Hirose RF Connector"
L1 L2 L4 L5 L6 L7 L8 L9 L10 L11: "Inductor SMD"
"Logo Bot" "Logo ESD" "Logo Recycling1" "Logo Semtech S": library part Logo, "Schematic symbol for Logo"
Q1: library part "Xtal GND", "Crystal with GND pins; 4 pins"
R1 R2 R3 R4 R5 R6 R7 R8 R9 R10 R11 R12 R13 R14 R15 R16 R17 R18 R19 R20 R21 R22 R23 R24 R25 R26 R27 R28 R29 R30 R31 R32 R33 R34 R35 R36 R37 R38 R39 R40 R41 R42 R43 R44 R45 R46 R47 R48 R49 R50 R51 R52: "Resistor SMD - IEC symbol version"
Shield: library part Shield, "Shield - EMI Gasket - Standard Surface Mount Shields"
U1: "SX1280 - Ultra low power RF transceiver"
U2: library part "CG2214M6 RF Switch", "CG2214M6 RF Switch"
U3 U8: "NC7SZ04 - TinyLogic HS Single Inverter - Fairchild Semi"
U4: "Ultra Low Power, Smart Proximity Sensor for SAR"
U5: library part MAX-7Q, "MAX-7Q; U-Blox; 7 GPS/GNSS modules"
U6: "Micropower USB Power Manager With Li-Ion Charger,  LDO and Buck Regulator"
U7: "LTC3127EDD#PBF - 1A Buck-Boost DC/DC  Converter with Programmable  Input Current Limit"
U9: "Triple 3-Input OR Gate, 6-Pin"
U10: "Xtrinsic MMA8451Q 3-Axis, 14-bit/8-bit Digital Accelerometer"
VDD_RADIO: "Jumper Wire"

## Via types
v1: diameter 0.5, hole 0.25, Top Layer to Bottom Layer, tented both sides, 1338 vias
v2: diameter 0.6, hole 0.3, Top Layer to Bottom Layer, tented both sides, 107 vias
v3: diameter 0.5, hole 0.3, Top Layer to Bottom Layer, tented top, 10 vias
v4: diameter 0.6, hole 0.3, Top Layer to Bottom Layer, tented top, 9 vias
v5: diameter 0.4, hole 0.2, Top Layer to Bottom Layer, tented both sides, 4 vias
v6: diameter 0.66, hole 0.33, Top Layer to Bottom Layer, tented top, 2 vias

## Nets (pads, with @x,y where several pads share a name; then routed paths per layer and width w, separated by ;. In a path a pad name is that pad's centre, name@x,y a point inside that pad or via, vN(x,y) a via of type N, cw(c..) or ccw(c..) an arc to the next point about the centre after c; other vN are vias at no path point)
ANT_DIV: C22.2 R16.1 U2.4 U3.2 | length 99.7
  Top Layer w0.2: R16.1@42.217,6.6 42.85,7.233 v1(42.85,7.25) ; v1(72.1,15.7) U3.2@72.1,17.789 ; U2.4@73.15,29.48 73.15,30.6 C22.2@73.25,30.7 v1(73.875,30.7)
  MidLayer1 w0.2: v1(49.192,13.55) 49.2,13.558 v1(49.2,21.25)
  MidLayer2 w0.2: v1(42.85,7.25) 42.9,7.25 49.2,13.55 69.95,13.55 v1(72.1,15.7) ; v1(49.2,21.25) 47.1,23.35 47.1,34.3 56.35,43.55 68.75,43.55 73.875,38.425 v1(73.875,30.7)
ANT_DIV_INV: C21.2 U2.6 U3.4 | length 10
  Top Layer w0.2: U3.4@72.75,19.689 v1(72.75,20.5) ; U2.6@73.15,28.52 73.15,27.425 C21.2@73.25,27.325 v1(73.875,27.325)
  MidLayer2 w0.2: v1(72.75,20.5) 72.75,22.15 73.875,23.275 v1(73.875,27.325) v1@73.875,27.35
ANT_SW: J4.4 R16.2 | length 1.7
  Top Layer w0.2: R16.2@41.117,6.6 41.12,6.597 J4.4@41.12,4.89
BUSY: R5.2 U1.7 | length 33.2
  Top Layer w0.2: R5.2@37.39,47.6 38.04,46.95 40.95,46.95 44.55,43.35 50.445,43.35 51.35,42.445 51.35,36.056 53.556,33.85 55.35,33.85 59.2,30 U1.7@59.6,30
BUSY_0: J1.4 R5.1 | length 4.9
  Top Layer w0.2: R5.1@37.39,48.7 37.39,51.96 J1.4@38.58,53.15
CS2: L9.1 U4.3 | length 66
  Top Layer w0.2: U4.3@39.611,40.75 40.97,40.75 41.195,40.975 v1(41.2,40.975) ; v1(82.97,19.02) L9.1@83.874,19.02
  MidLayer2 w0.2: v1(41.2,40.975) 41.4,40.775 v1(41.4,29.35) ; v1(41.4,25.65) 41.4,23.5 42.55,22.35 42.55,22.301 48.651,16.2 79,16.2 81.82,19.02 v1@82.95,19.02
  Bottom Layer w0.2: v1@41.4,25.601 v1(41.4,29.35)
CS3: L10.1 U4.2 | length 49.9
  Top Layer w0.2: U4.2@39.611,40.35 41.55,40.35 v1(42.15,40.95) ; v1(82.95,38.979) L10.1@83.874,38.979
  MidLayer2 w0.2: v1(42.15,40.95) 47.7,46.5 74.05,46.5 81.571,38.979 v1(82.95,38.979)
CTS: J_UART.2 R3.1 | length 11.6
  Top Layer w0.2: J_UART.2@20.69,55.69 20.69,50.163 22.153,48.7 R3.1@26.2,48.7
DIO1: U1.8 U9.3 | length 6.6
  Top Layer w0.2: U9.3@54.569,33.23 55.436,33.23 59.167,29.5 U1.8@59.65,29.5
DIO2: U1.9 U9.1 | length 6.3
  Top Layer w0.2: U9.1@54.569,31.93 56.17,31.93 59.1,29 U1.9@59.65,29
DIO3: U1.10 U9.6 | length 8.4
  Top Layer w0.2: U9.6@52.669,31.93 52.87,31.93 53.32,31.48 56.073,31.48 59.054,28.5 U1.10@59.65,28.5
DIOX: J1.6 R6.1 | length 5
  Top Layer w0.2: R6.1@32.286,48.7 32.3,48.714 32.3,51.95 J1.6@33.5,53.15
DISP_RESET: J3.3 J3_DISP.3 | length 2.5
  Top Layer w0.2: J3_DISP.3@15.58,2.35 J3.3@15.58,4.89
F_CS: J1.7 J1_DISP.7 | length 2.5
  Top Layer w0.2: J1_DISP.7@30.96,50.61 J1.7@30.96,53.15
